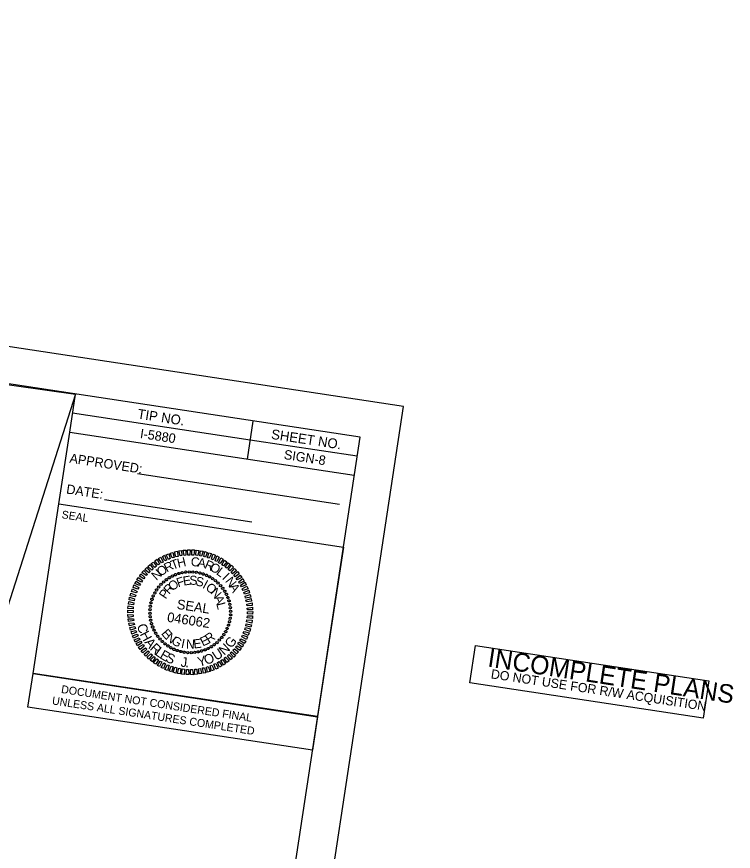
# Model space of a CAD drawing. Extents: x 1640181 to 1642275, y 841730 to 843072.
# Drawn here: x 1641809 to 1642275, y 842529 to 843071 of the extents above; entities that cross this region are included whole.
import ezdxf

# ---------------------------------------------------------------- set-up
doc = ezdxf.new("R2010")
doc.units = 0
for name, color, linetype in [('Default', 7, 'Continuous'), ('Level 11', 7, 'Continuous'), ('Level 2', 7, 'Continuous'), ('Level 23', 7, 'Continuous'), ('Level 3', 7, 'Continuous'), ('Level 33', 7, 'Continuous'), ('Level 35', 7, 'Continuous'), ('Level 6', 7, 'Continuous'), ('Level 8', 7, 'Continuous'), ('Level 9', 7, 'Continuous')]:
    doc.layers.add(name, color=color, linetype=linetype)

msp = doc.modelspace()

# ---------------------------------------------------------------- linework, layer by layer
at = {"layer": 'Level 2'}
msp.add_lwpolyline([(1640226.71, 841983.66), (1641895.61, 841730.39), (1642060.65, 842817.94), (1640391.76, 843071.21)], close=True, dxfattribs=at)
msp.add_lwpolyline([(1640226.71, 841983.66), (1641895.61, 841730.39), (1642060.65, 842817.94), (1640391.76, 843071.21)], close=True, dxfattribs=at)
at = {"layer": 'Level 23'}
for p, q in [((1641843.73, 842801.42), (1641847.47, 842826.08)), ((1641836.65, 842754.77), (1641843.73, 842801.42)), ((1641819.93, 842644.63), (1641836.65, 842754.77)), ((1642004.79, 842616.49), (1641819.93, 842644.63))]:
    msp.add_line(p, q, dxfattribs=at)
at = {"layer": 'Level 3'}
msp.add_lwpolyline([(1642032.34, 842798.03), (1640550.03, 843022.98), (1640392.33, 841983.81), (1641874.64, 841758.86)], close=True, dxfattribs=at)
at = {"layer": 'Level 33'}
for p, q in [((1641843.73, 842801.42), (1641847.47, 842826.08)), ((1641845.64, 842814.01), (1641961.07, 842796.48)), ((1641959.16, 842783.89), (1641962.9, 842808.57)), ((1641959.16, 842783.89), (1641962.9, 842808.57)), ((1641843.73, 842801.42), (1642028.6, 842773.35)), ((1641961.07, 842796.48), (1642030.51, 842785.94)), ((1642032.34, 842798.03), (1642032.34, 842798.03)), ((1642032.34, 842798.03), (1642032.34, 842798.03)), ((1642032.34, 842798.03), (1642032.34, 842798.03)), ((1642032.34, 842798.03), (1642032.34, 842798.03)), ((1642032.34, 842798.03), (1642032.34, 842798.03)), ((1642032.34, 842798.03), (1642032.34, 842798.03)), ((1642032.34, 842798.03), (1642032.34, 842798.03)), ((1642032.34, 842798.03), (1642032.34, 842798.03)), ((1641887.89, 842774.57), (1642019, 842754.67)), ((1641866.43, 842757.69), (1641962.11, 842743.17))]:
    msp.add_line(p, q, dxfattribs=at)
at = {"layer": 'Level 35'}
msp.add_lwpolyline([(1642103.72, 842638.55), (1642107.4, 842662.75), (1642258.82, 842639.77), (1642255.15, 842615.57)], close=True, dxfattribs=at)
at = {"layer": 'Level 6'}
msp.add_lwpolyline([(1640495.4, 842368.43), (1640578.69, 842512.77), (1640617.73, 842617.59), (1640629.05, 842742.44), (1640614.97, 842767.52), (1640908.06, 842958.77), (1641847.47, 842826.08), (1641796.56, 842667.29), (1641752.38, 842181.83), (1641755.46, 842119.79), (1641647.87, 841984.79), (1641620.53, 841871.11), (1641550.27, 841881.77), (1641474.89, 841869.36), (1641375.09, 841879.22), (1641370.37, 841845.01), (1641259.98, 841852.14), (1640964.13, 841969.33), (1640641.82, 842236.89)], close=True, dxfattribs=at)
at = {"layer": 'Level 8'}
for p, q in [((1641816.62, 842622.83), (1641819.92, 842644.55)), ((1641819.92, 842644.55), (1642004.79, 842616.49)), ((1642001.5, 842594.77), (1641816.62, 842622.83)), ((1642004.79, 842616.48), (1642001.49, 842594.76))]:
    msp.add_line(p, q, dxfattribs=at)
at = {"layer": 'Level 9'}
for p, q in [((1641836.65, 842754.77), (1641843.73, 842801.42)), ((1641908.38, 842706.84), (1641908.38, 842706.84)), ((1641910.37, 842707.89), (1641910.37, 842707.89)), ((1641912.49, 842708.82), (1641912.49, 842708.82)), ((1641914.65, 842709.59), (1641914.65, 842709.59)), ((1641916.84, 842710.14), (1641916.84, 842710.14)), ((1641919.1, 842710.47), (1641919.1, 842710.47)), ((1641921.43, 842710.58), (1641921.43, 842710.58)), ((1641923.7, 842710.59), (1641923.7, 842710.59)), ((1641925.99, 842710.34), (1641925.99, 842710.34)), ((1641928.25, 842709.88), (1641928.25, 842709.88)), ((1641930.43, 842709.22), (1641930.43, 842709.22)), ((1641932.55, 842708.46), (1641932.55, 842708.46)), ((1641934.62, 842707.44), (1641934.62, 842707.44)), ((1641936.57, 842706.23), (1641936.57, 842706.23)), ((1641901.5, 842700.8), (1641901.5, 842700.8)), ((1641903.05, 842702.49), (1641903.05, 842702.49)), ((1641904.69, 842704.12), (1641904.69, 842704.12)), ((1641906.46, 842705.52), (1641906.46, 842705.52)), ((1641938.46, 842704.92), (1641938.46, 842704.92)), ((1641940.15, 842703.38), (1641940.15, 842703.38)), ((1641941.77, 842701.73), (1641941.77, 842701.73)), ((1641898.98, 842696.97), (1641898.98, 842696.97)), ((1641900.19, 842698.92), (1641900.19, 842698.92)), ((1641943.17, 842699.96), (1641943.17, 842699.96)), ((1641944.5, 842698.05), (1641944.5, 842698.05)), ((1641945.55, 842696.06), (1641945.55, 842696.06)), ((1641896.55, 842690.59), (1641896.55, 842690.59)), ((1641897.21, 842692.77), (1641897.21, 842692.77)), ((1641897.97, 842694.89), (1641897.97, 842694.89)), ((1641946.48, 842693.93), (1641946.48, 842693.93)), ((1641947.24, 842691.77), (1641947.24, 842691.77)), ((1641895.83, 842686.05), (1641895.83, 842686.05)), ((1641896.09, 842688.33), (1641896.09, 842688.33)), ((1641922.04, 842684.38), (1641922.04, 842684.38)), ((1641947.8, 842689.59), (1641947.8, 842689.59)), ((1641948.13, 842687.33), (1641948.13, 842687.33)), ((1641948.24, 842684.99), (1641948.24, 842684.99)), ((1641895.85, 842683.78), (1641895.85, 842683.78)), ((1641895.95, 842681.44), (1641895.95, 842681.44)), ((1641896.29, 842679.18), (1641896.29, 842679.18)), ((1641947.99, 842680.43), (1641947.99, 842680.43)), ((1641948.25, 842682.72), (1641948.25, 842682.72)), ((1641896.84, 842677), (1641896.84, 842677)), ((1641897.6, 842674.84), (1641897.6, 842674.84)), ((1641946.11, 842673.88), (1641946.11, 842673.88)), ((1641946.87, 842675.99), (1641946.87, 842675.99)), ((1641947.53, 842678.17), (1641947.53, 842678.17)), ((1641898.53, 842672.71), (1641898.53, 842672.71)), ((1641899.58, 842670.72), (1641899.58, 842670.72)), ((1641900.91, 842668.8), (1641900.91, 842668.8)), ((1641943.89, 842669.85), (1641943.89, 842669.85)), ((1641945.1, 842671.8), (1641945.1, 842671.8)), ((1641902.31, 842667.03), (1641902.31, 842667.03)), ((1641903.93, 842665.39), (1641903.93, 842665.39)), ((1641905.63, 842663.84), (1641905.63, 842663.84)), ((1641937.62, 842663.25), (1641937.62, 842663.25)), ((1641939.39, 842664.65), (1641939.39, 842664.65)), ((1641941.03, 842666.28), (1641941.03, 842666.28)), ((1641942.58, 842667.97), (1641942.58, 842667.97)), ((1641907.51, 842662.54), (1641907.51, 842662.54)), ((1641909.46, 842661.33), (1641909.46, 842661.33)), ((1641911.54, 842660.31), (1641911.54, 842660.31)), ((1641913.65, 842659.55), (1641913.65, 842659.55)), ((1641915.83, 842658.89), (1641915.83, 842658.89)), ((1641918.09, 842658.43), (1641918.09, 842658.43)), ((1641920.38, 842658.18), (1641920.38, 842658.18)), ((1641922.65, 842658.19), (1641922.65, 842658.19)), ((1641924.98, 842658.3), (1641924.98, 842658.3)), ((1641927.24, 842658.63), (1641927.24, 842658.63)), ((1641929.43, 842659.18), (1641929.43, 842659.18)), ((1641931.59, 842659.95), (1641931.59, 842659.95)), ((1641933.72, 842660.87), (1641933.72, 842660.87)), ((1641935.7, 842661.93), (1641935.7, 842661.93))]:
    msp.add_line(p, q, dxfattribs=at)
for points in [[(1641836.65, 842754.77), (1642021.52, 842726.72), (1642004.8, 842616.58), (1641819.93, 842644.63)], [(1641907.96, 842718.71), (1641906.42, 842721.77), (1641908.14, 842722.38), (1641909.03, 842719.2)], [(1641910.36, 842719.66), (1641909.09, 842722.78), (1641910.79, 842723.29), (1641911.56, 842719.97)], [(1641912.78, 842720.44), (1641911.84, 842723.63), (1641913.48, 842724.04), (1641914.12, 842720.58)], [(1641915.44, 842720.93), (1641914.66, 842724.2), (1641916.33, 842724.45), (1641916.57, 842721.15)], [(1641918.01, 842721.27), (1641917.36, 842724.68), (1641919.17, 842724.81), (1641919.14, 842721.38)], [(1641920.58, 842721.51), (1641920.19, 842724.94), (1641921.92, 842724.86), (1641921.84, 842721.5)], [(1641923.11, 842721.49), (1641922.98, 842724.88), (1641924.77, 842724.85), (1641924.37, 842721.47)], [(1641925.73, 842721.4), (1641925.92, 842724.8), (1641927.63, 842724.52), (1641926.97, 842721.18)], [(1641928.21, 842721.01), (1641928.66, 842724.38), (1641930.37, 842724.1), (1641929.45, 842720.79)], [(1641930.78, 842720.51), (1641931.44, 842723.85), (1641933.11, 842723.31), (1641932, 842720.14)], [(1641933.22, 842719.76), (1641934.13, 842723.02), (1641935.8, 842722.53), (1641934.44, 842719.44)], [(1641899.09, 842713.52), (1641896.73, 842716), (1641898.19, 842717.02), (1641900.03, 842714.24)], [(1641901.04, 842715.1), (1641899.07, 842717.69), (1641900.48, 842718.77), (1641902.13, 842715.7)], [(1641903.33, 842716.43), (1641901.44, 842719.22), (1641902.98, 842720.12), (1641904.41, 842716.97)], [(1641905.51, 842717.72), (1641903.95, 842720.62), (1641905.43, 842721.43), (1641906.73, 842718.19)], [(1641935.78, 842718.84), (1641936.75, 842722.14), (1641938.46, 842721.49), (1641936.84, 842718.43)], [(1641938.18, 842717.83), (1641939.39, 842720.94), (1641940.92, 842720.21), (1641939.22, 842717.32)], [(1641940.39, 842716.59), (1641942.02, 842719.69), (1641943.38, 842718.88), (1641941.53, 842716.06)], [(1641942.59, 842715.29), (1641944.29, 842718.17), (1641945.8, 842717.23), (1641943.65, 842714.57)], [(1641893.36, 842708.17), (1641890.67, 842710.11), (1641891.9, 842711.42), (1641894.32, 842708.99)], [(1641895.19, 842710.03), (1641892.63, 842712.17), (1641893.82, 842713.54), (1641896, 842710.93)], [(1641897.01, 842711.79), (1641894.59, 842714.17), (1641895.91, 842715.37), (1641897.86, 842712.63)], [(1641944.81, 842713.78), (1641946.61, 842716.54), (1641948.04, 842715.46), (1641945.71, 842713.02)], [(1641946.65, 842712.11), (1641948.86, 842714.87), (1641950.06, 842713.6), (1641947.7, 842711.33)], [(1641948.56, 842710.27), (1641950.86, 842712.86), (1641952.06, 842711.54), (1641949.45, 842709.41)], [(1641890.46, 842703.86), (1641887.41, 842705.48), (1641888.4, 842706.98), (1641891.13, 842704.93)], [(1641891.82, 842706.1), (1641889.04, 842707.8), (1641890.03, 842709.3), (1641892.57, 842707.01)], [(1641950.32, 842708.4), (1641952.8, 842710.81), (1641953.88, 842709.4), (1641951.2, 842707.49)], [(1641951.94, 842706.33), (1641954.49, 842708.47), (1641955.57, 842707.06), (1641952.61, 842705.4)], [(1641953.5, 842704.23), (1641956.2, 842706.24), (1641957.1, 842704.69), (1641954.09, 842703.09)], [(1641888.01, 842699.33), (1641884.89, 842700.44), (1641885.48, 842702.1), (1641888.57, 842700.37)], [(1641889.12, 842701.72), (1641886.03, 842703.08), (1641886.92, 842704.6), (1641889.84, 842702.73)], [(1641954.79, 842702), (1641957.62, 842703.83), (1641958.4, 842702.2), (1641955.28, 842700.93)], [(1641955.85, 842699.69), (1641958.86, 842701.29), (1641959.64, 842699.61), (1641956.44, 842698.56)], [(1641886.24, 842694.35), (1641882.96, 842695.1), (1641883.4, 842696.84), (1641886.66, 842695.56)], [(1641887, 842696.94), (1641883.85, 842697.78), (1641884.45, 842699.5), (1641887.56, 842697.97)], [(1641956.89, 842697.23), (1641960.04, 842698.66), (1641960.5, 842696.96), (1641957.38, 842696.16)], [(1641957.63, 842694.86), (1641960.9, 842696.01), (1641961.35, 842694.26), (1641958, 842693.65)], [(1641885.24, 842689.31), (1641881.86, 842689.61), (1641882.09, 842691.37), (1641885.41, 842690.56)], [(1641885.64, 842691.9), (1641882.29, 842692.45), (1641882.62, 842694.15), (1641885.91, 842693.13)], [(1641958.24, 842692.3), (1641961.58, 842693.23), (1641961.93, 842691.54), (1641958.61, 842691.14)], [(1641958.73, 842689.7), (1641962.21, 842690.45), (1641962.29, 842688.7), (1641958.95, 842688.57)], [(1641884.93, 842684.18), (1641881.46, 842683.91), (1641881.54, 842685.69), (1641884.89, 842685.46)], [(1641884.95, 842686.71), (1641881.53, 842686.75), (1641881.66, 842688.53), (1641885.01, 842687.97)], [(1641959.02, 842687.13), (1641962.42, 842687.68), (1641962.49, 842685.88), (1641959.19, 842686)], [(1641959.15, 842684.58), (1641962.62, 842684.86), (1641962.54, 842683.07), (1641959.19, 842683.31)], [(1641885.06, 842681.63), (1641881.66, 842681.09), (1641881.59, 842682.89), (1641884.9, 842682.76)], [(1641885.35, 842679.06), (1641881.87, 842678.32), (1641881.79, 842680.07), (1641885.13, 842680.2)], [(1641958.84, 842679.45), (1641962.23, 842679.16), (1641961.99, 842677.4), (1641958.67, 842678.21)], [(1641959.13, 842682.05), (1641962.56, 842682.02), (1641962.42, 842680.24), (1641959.07, 842680.8)], [(1641885.84, 842676.47), (1641882.5, 842675.54), (1641882.15, 842677.22), (1641885.47, 842677.62)], [(1641886.45, 842673.9), (1641883.19, 842672.76), (1641882.73, 842674.51), (1641886.09, 842675.11)], [(1641957.85, 842674.42), (1641961.12, 842673.66), (1641960.68, 842671.93), (1641957.42, 842673.21)], [(1641958.44, 842676.87), (1641961.79, 842676.32), (1641961.46, 842674.62), (1641958.17, 842675.64)], [(1641887.19, 842671.54), (1641884.04, 842670.11), (1641883.59, 842671.81), (1641886.7, 842672.6)], [(1641888.23, 842669.08), (1641885.22, 842667.47), (1641884.44, 842669.16), (1641887.64, 842670.21)], [(1641956.07, 842669.43), (1641959.19, 842668.33), (1641958.6, 842666.67), (1641955.51, 842668.4)], [(1641957.08, 842671.83), (1641960.23, 842670.98), (1641959.64, 842669.27), (1641956.52, 842670.8)], [(1641889.29, 842666.77), (1641886.46, 842664.93), (1641885.68, 842666.57), (1641888.8, 842667.84)], [(1641890.58, 842664.54), (1641887.88, 842662.53), (1641886.98, 842664.07), (1641889.99, 842665.68)], [(1641892.14, 842662.43), (1641889.59, 842660.3), (1641888.51, 842661.71), (1641891.48, 842663.37)], [(1641952.26, 842662.66), (1641955.04, 842660.97), (1641954.05, 842659.47), (1641951.51, 842661.76)], [(1641953.62, 842664.91), (1641956.67, 842663.29), (1641955.68, 842661.78), (1641952.95, 842663.84)], [(1641954.96, 842667.05), (1641958.05, 842665.69), (1641957.16, 842664.17), (1641954.24, 842666.04)], [(1641893.77, 842660.37), (1641891.28, 842657.96), (1641890.2, 842659.37), (1641892.88, 842661.28)], [(1641895.52, 842658.5), (1641893.22, 842655.9), (1641892.03, 842657.23), (1641894.63, 842659.36)], [(1641897.44, 842656.66), (1641895.22, 842653.9), (1641894.02, 842655.17), (1641896.38, 842657.43)], [(1641948.89, 842658.74), (1641951.45, 842656.6), (1641950.26, 842655.23), (1641948.08, 842657.84)], [(1641950.72, 842660.6), (1641953.41, 842658.66), (1641952.18, 842657.34), (1641949.76, 842659.78)], [(1641899.27, 842654.99), (1641897.47, 842652.22), (1641896.04, 842653.31), (1641898.37, 842655.74)], [(1641901.49, 842653.48), (1641899.79, 842650.59), (1641898.28, 842651.53), (1641900.43, 842654.2)], [(1641903.69, 842652.18), (1641902.06, 842649.08), (1641900.7, 842649.89), (1641902.55, 842652.7)], [(1641940.75, 842652.33), (1641942.64, 842649.55), (1641941.1, 842648.65), (1641939.67, 842651.79)], [(1641943.04, 842653.66), (1641945.01, 842651.08), (1641943.6, 842650), (1641941.96, 842653.07)], [(1641944.99, 842655.25), (1641947.35, 842652.77), (1641945.89, 842651.75), (1641944.05, 842654.53)], [(1641947.07, 842656.97), (1641949.49, 842654.59), (1641948.17, 842653.4), (1641946.22, 842656.14)], [(1641905.9, 842650.94), (1641904.69, 842647.83), (1641903.16, 842648.56), (1641904.86, 842651.44)], [(1641908.3, 842649.93), (1641907.33, 842646.63), (1641905.62, 842647.28), (1641907.25, 842650.33)], [(1641910.87, 842649), (1641909.95, 842645.75), (1641908.28, 842646.24), (1641909.64, 842649.33)], [(1641913.3, 842648.26), (1641912.64, 842644.92), (1641910.97, 842645.46), (1641912.08, 842648.63)], [(1641915.87, 842647.75), (1641915.42, 842644.39), (1641913.71, 842644.67), (1641914.63, 842647.97)], [(1641918.35, 842647.37), (1641918.16, 842643.97), (1641916.45, 842644.25), (1641917.11, 842647.59)], [(1641920.97, 842647.28), (1641921.1, 842643.89), (1641919.31, 842643.92), (1641919.71, 842647.29)], [(1641923.5, 842647.26), (1641923.89, 842643.83), (1641922.16, 842643.9), (1641922.24, 842647.27)], [(1641926.07, 842647.5), (1641926.72, 842644.08), (1641924.91, 842643.96), (1641924.94, 842647.38)], [(1641928.65, 842647.84), (1641929.42, 842644.57), (1641927.75, 842644.32), (1641927.51, 842647.62)], [(1641931.3, 842648.33), (1641932.24, 842645.14), (1641930.6, 842644.73), (1641929.96, 842648.19)], [(1641933.72, 842649.11), (1641934.99, 842645.98), (1641933.29, 842645.47), (1641932.52, 842648.79)], [(1641936.12, 842650.05), (1641937.66, 842647), (1641935.94, 842646.38), (1641935.05, 842649.56)], [(1641938.57, 842651.04), (1641940.13, 842648.14), (1641938.66, 842647.34), (1641937.35, 842650.57)]]:
    msp.add_lwpolyline(points, close=True, dxfattribs=at)
for centre, major_axis in [((1641921.41, 842710.6), (-0.018, 0.753)), ((1641906.49, 842705.5), (-0.447, 0.606)), ((1641908.39, 842706.78), (-0.392, 0.643)), ((1641910.39, 842707.88), (-0.334, 0.675)), ((1641912.48, 842708.81), (-0.274, 0.701)), ((1641914.65, 842709.55), (-0.212, 0.722)), ((1641916.87, 842710.1), (-0.148, 0.738)), ((1641919.13, 842710.45), (-0.084, 0.748)), ((1641923.7, 842710.56), (0.048, 0.751)), ((1641925.98, 842710.31), (0.113, 0.744)), ((1641928.22, 842709.87), (0.177, 0.732)), ((1641930.42, 842709.24), (0.241, 0.714)), ((1641932.55, 842708.41), (0.302, 0.69)), ((1641934.61, 842707.4), (0.361, 0.661)), ((1641936.57, 842706.22), (0.417, 0.627)), ((1641901.55, 842700.76), (-0.588, 0.47)), ((1641903.06, 842702.48), (-0.545, 0.52)), ((1641904.71, 842704.07), (-0.498, 0.565)), ((1641938.41, 842704.87), (0.47, 0.588)), ((1641940.14, 842703.37), (0.52, 0.545)), ((1641941.72, 842701.72), (0.565, 0.498)), ((1641943.16, 842699.94), (0.606, 0.447)), ((1641898.01, 842694.9), (-0.69, 0.302)), ((1641899.02, 842696.95), (-0.661, 0.361)), ((1641900.2, 842698.91), (-0.627, 0.417)), ((1641944.43, 842698.04), (0.643, 0.392)), ((1641945.54, 842696.03), (0.675, 0.334)), ((1641896.55, 842690.56), (-0.732, 0.177)), ((1641897.19, 842692.76), (-0.714, 0.241)), ((1641946.47, 842693.94), (0.701, 0.274)), ((1641947.21, 842691.78), (0.722, 0.212)), ((1641947.75, 842689.55), (0.738, 0.148)), ((1641895.82, 842683.76), (-0.753, -0.018)), ((1641895.87, 842686.04), (-0.751, 0.048)), ((1641896.11, 842688.32), (-0.744, 0.113)), ((1641948.11, 842687.29), (0.748, 0.084)), ((1641948.26, 842685.01), (0.753, 0.018)), ((1641895.97, 842681.47), (-0.748, -0.084)), ((1641896.33, 842679.21), (-0.738, -0.148)), ((1641947.53, 842678.2), (0.732, -0.177)), ((1641947.97, 842680.45), (0.744, -0.113)), ((1641948.22, 842682.72), (0.751, -0.048)), ((1641896.88, 842676.99), (-0.722, -0.212)), ((1641897.62, 842674.83), (-0.701, -0.274)), ((1641898.54, 842672.73), (-0.675, -0.334)), ((1641946.07, 842673.87), (0.69, -0.302)), ((1641946.89, 842676.01), (0.714, -0.241)), ((1641899.65, 842670.73), (-0.643, -0.392)), ((1641900.92, 842668.83), (-0.606, -0.447)), ((1641942.53, 842668.01), (0.588, -0.47)), ((1641943.88, 842669.86), (0.627, -0.417)), ((1641945.06, 842671.82), (0.661, -0.361)), ((1641902.36, 842667.05), (-0.565, -0.498)), ((1641903.94, 842665.4), (-0.52, -0.545)), ((1641905.67, 842663.89), (-0.47, -0.588)), ((1641907.52, 842662.55), (-0.417, -0.627)), ((1641935.69, 842661.99), (0.392, -0.643)), ((1641937.59, 842663.26), (0.447, -0.606)), ((1641939.38, 842664.7), (0.498, -0.565)), ((1641941.02, 842666.29), (0.545, -0.52)), ((1641909.47, 842661.36), (-0.361, -0.661)), ((1641911.53, 842660.35), (-0.302, -0.69)), ((1641913.66, 842659.53), (-0.241, -0.714)), ((1641915.86, 842658.89), (-0.177, -0.732)), ((1641918.11, 842658.45), (-0.113, -0.744)), ((1641920.38, 842658.21), (-0.048, -0.751)), ((1641922.67, 842658.16), (0.018, -0.753)), ((1641924.95, 842658.32), (0.084, -0.748)), ((1641927.21, 842658.67), (0.148, -0.738)), ((1641929.43, 842659.22), (0.212, -0.722)), ((1641931.6, 842659.96), (0.274, -0.701)), ((1641933.69, 842660.88), (0.334, -0.675))]:
    msp.add_ellipse(centre, major_axis=major_axis, ratio=0.999708, dxfattribs=at)

# ---------------------------------------------------------------- texts
at = {"layer": 'Default'}
for s, rotation, p in [('C', 288.5705, (1641887.24, 842675.78)), ('H', 298.0143, (1641889.12, 842670.18)), ('G', 53.1704, (1641948.89, 842660.59)), ('A', 307.8541, (1641892.03, 842664.76)), ('R', 316.5667, (1641895.34, 842660.44)), ('N', 42.5995, (1641944.07, 842656.07)), ('L', 323.939, (1641898.63, 842657.21)), ('E', 330.1231, (1641901.69, 842654.85)), ('S', 337.1298, (1641905.45, 842652.59)), ('O', 21.4119, (1641932.35, 842650.02)), ('U', 32.8054, (1641938.93, 842652.74)), ('J', 354.4028, (1641915.63, 842649.09)), ('Y', 13.6132, (1641927.6, 842648.94)), ('.', 359.5846, (1641918.84, 842648.65))]:
    msp.add_text(s, height=6.27, rotation=rotation, dxfattribs=at).set_placement(p)
at = {"layer": 'Level 11'}
for s, p in [('APPROVED:', (1641843.34, 842781.6)), ('DATE:', (1641841.22, 842761.55))]:
    msp.add_text(s, height=6.11, rotation=351.3656, dxfattribs=at).set_placement(p)
at = {"layer": 'Level 33'}
for s, height, p in [('TIP NO.', 6.358, (1641887.41, 842810.25)), ('I-5880', 6.11, (1641889.17, 842797.62)), ('SHEET NO.', 6.358, (1641974.33, 842797.05)), ('SIGN-8', 6.11, (1641982.59, 842783.95)), ('SEAL', 5.094, (1641838.3, 842745.51))]:
    msp.add_text(s, height=height, rotation=351.3656, dxfattribs=at).set_placement(p)
at = {"layer": 'Level 35'}
for s, height, p in [('INCOMPLETE PLANS', 12.0025, (1642114.77, 842649.2)), ('DO NOT USE FOR R/W ACQUISITION', 6.0012, (1642117.03, 842641.53))]:
    msp.add_text(s, height=height, rotation=351.3707, dxfattribs=at).set_placement(p)
at = {"layer": 'Level 8'}
for s, p in [('DOCUMENT NOT CONSIDERED FINAL', (1641837.94, 842632.03)), ('UNLESS ALL SIGNATURES COMPLETED', (1641832.02, 842624.61))]:
    msp.add_text(s, height=5.1412, rotation=351.3707, dxfattribs=at).set_placement(p)
at = {"layer": 'Level 9'}
for s, height, rotation, p in [('R', 5.9, 27.3912, (1641906.82, 842710.16)), ('T', 5.9, 20.1904, (1641910.65, 842711.97)), ('H', 5.9, 12.9901, (1641914.25, 842713.23)), ('C', 5.9, 358.5905, (1641922.4, 842714.25)), ('A', 5.9, 351.391, (1641926.54, 842714.01)), ('R', 5.9, 336.9918, (1641930.86, 842713.22)), ('N', 5.9, 41.7942, (1641900.03, 842704.74)), ('O', 5.9, 34.5924, (1641902.81, 842707.43)), ('O', 5.9, 329.7918, (1641934.23, 842711.98)), ('L', 5.9, 322.5915, (1641938.53, 842709.45)), ('F', 5.9, 18.3377, (1641914.23, 842700.52)), ('E', 5.9, 8.9817, (1641917.76, 842701.63)), ('S', 5.9, 359.6263, (1641921.48, 842702.24)), ('S', 5.9, 350.2711, (1641925.22, 842701.79)), ('I', 5.9, 315.3908, (1641942.4, 842706.4)), ('N', 5.9, 308.1896, (1641944.41, 842704.49)), ('R', 5.9, 46.4103, (1641908.25, 842695.62)), ('O', 5.9, 37.0519, (1641910.4, 842697.92)), ('I', 5.9, 331.5603, (1641929.58, 842700.47)), ('O', 5.9, 322.2041, (1641931.55, 842699.46)), ('A', 5.9, 300.9878, (1641947.06, 842701.03)), ('P', 5.9, 55.7696, (1641906.14, 842692.53)), ('N', 5.9, 312.8473, (1641934.75, 842696.93)), ('SEAL', 6.273, 351.3707, (1641913.01, 842686.65)), ('A', 5.9, 294.1309, (1641937.34, 842693.83)), ('L', 5.9, 284.7715, (1641938.88, 842689.99)), ('046062', 6.275, 351.3707, (1641906.71, 842678.3)), ('E', 5.9, 310.6476, (1641902.87, 842670.44)), ('N', 5.9, 320.0046, (1641905.6, 842667.22)), ('G', 5.9, 329.3609, (1641909.23, 842664.36)), ('E', 5.9, 25.4948, (1641930.19, 842662.08)), ('R', 5.9, 34.8521, (1641934.19, 842664.03)), ('I', 5.9, 348.0719, (1641915.76, 842661.49)), ('N', 5.9, 357.4271, (1641919.21, 842660.86)), ('E', 5.9, 6.7824, (1641924.42, 842660.8))]:
    msp.add_text(s, height=height, rotation=rotation, dxfattribs=at).set_placement(p)

doc.saveas('drawing.dxf')
